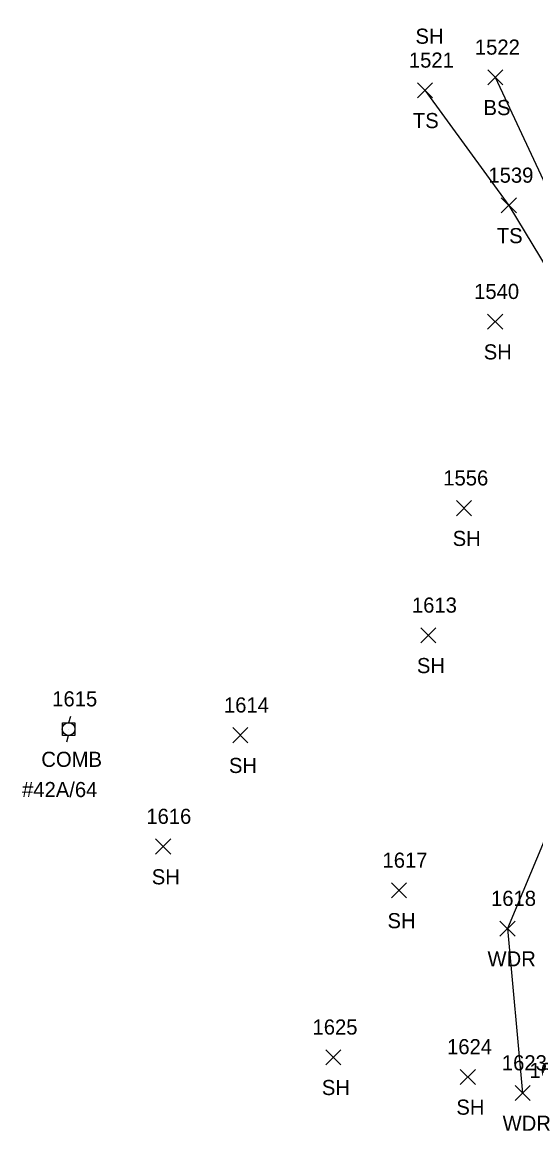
# Model space of a CAD drawing. Extents: x 1678553 to 1680768, y 787260 to 792325.
# Drawn here: x 1678553.1 to 1678621, y 787278.6 to 787425.2 of the extents above; entities that cross this region are included whole.
import ezdxf

# ---------------------------------------------------------------- set-up
doc = ezdxf.new("R2010")
doc.units = 0
for name, color, linetype in [('L_A', 7, 'Continuous'), ('L_I', 7, 'Continuous'), ('L_TIC', 7, 'Continuous'), ('LAWA', 7, 'Continuous'), ('LELB', 7, 'Continuous'), ('U_A', 7, 'Continuous'), ('U_C', 7, 'Continuous'), ('U_I', 7, 'Continuous'), ('UP', 7, 'Continuous')]:
    doc.layers.add(name, color=color, linetype=linetype)

msp = doc.modelspace()

# ---------------------------------------------------------------- linework, layer by layer
at = {"layer": 'L_TIC'}
for points in [[(1678614.65, 787416.95), (1678616.65, 787418.95)], [(1678616.65, 787416.95), (1678614.65, 787418.95)], [(1678605.34, 787415.23), (1678607.34, 787417.23)], [(1678607.34, 787415.23), (1678605.34, 787417.23)], [(1678616.44, 787400.01), (1678618.44, 787402.01)], [(1678618.44, 787400.01), (1678616.44, 787402.01)], [(1678614.63, 787384.63), (1678616.63, 787386.63)], [(1678616.63, 787384.63), (1678614.63, 787386.63)], [(1678610.52, 787359.96), (1678612.52, 787361.96)], [(1678612.52, 787359.96), (1678610.52, 787361.96)], [(1678605.79, 787343.14), (1678607.79, 787345.14)], [(1678607.79, 787343.14), (1678605.79, 787345.14)], [(1678580.92, 787329.93), (1678582.92, 787331.93)], [(1678582.92, 787329.93), (1678580.92, 787331.93)], [(1678570.71, 787315.2), (1678572.71, 787317.2)], [(1678572.71, 787315.2), (1678570.71, 787317.2)], [(1678601.9, 787309.4), (1678603.9, 787311.4)], [(1678603.9, 787309.4), (1678601.9, 787311.4)], [(1678616.26, 787304.35), (1678618.26, 787306.35)], [(1678618.26, 787304.35), (1678616.26, 787306.35)], [(1678593.21, 787287.33), (1678595.21, 787289.33)], [(1678595.21, 787287.33), (1678593.21, 787289.33)], [(1678611.01, 787284.73), (1678613.01, 787286.73)], [(1678613.01, 787284.73), (1678611.01, 787286.73)], [(1678618.26, 787282.6), (1678620.26, 787284.6)], [(1678620.26, 787282.6), (1678618.26, 787284.6)]]:
    msp.add_lwpolyline(points, dxfattribs=at)
at = {"layer": 'LAWA'}
msp.add_lwpolyline([(1678664.87, 787478.76), (1678656.17, 787475.05), (1678649.55, 787452.64), (1678645.06, 787437.85), (1678645.53, 787417.53), (1678643.94, 787403.04), (1678640.14, 787385.56), (1678638.68, 787382.05), (1678636.34, 787358.01), (1678630, 787335.83), (1678617.26, 787305.35), (1678619.26, 787283.6)], dxfattribs=at)
at = {"layer": 'LELB'}
for points in [[(1678615.65, 787417.95), (1678623.59, 787400.99), (1678633.57, 787392.81), (1678638.68, 787382.05)], [(1678606.34, 787416.23), (1678617.44, 787401.01), (1678626.85, 787385.47), (1678635.93, 787378.61), (1678632.1, 787358.6), (1678630, 787335.83)]]:
    msp.add_lwpolyline(points, dxfattribs=at)
at = {"layer": 'UP'}
for p, q in [((1678558.37, 787330.9), (1678558.37, 787332.57)), ((1678558.37, 787332.57), (1678560.03, 787332.57)), ((1678559.45, 787333.4), (1678559.2, 787332.57)), ((1678560.03, 787332.57), (1678560.03, 787330.9)), ((1678559.2, 787331.74), (1678559.2, 787331.74)), ((1678560.03, 787330.9), (1678558.37, 787330.9)), ((1678558.95, 787330.07), (1678559.2, 787330.9))]:
    msp.add_line(p, q, dxfattribs=at)
msp.add_circle((1678559.2, 787331.74), 0.833, dxfattribs=at)

# ---------------------------------------------------------------- texts
at = {"layer": 'L_A'}
for s, p in [('SH', (1678605.09, 787422.39)), ('BS', (1678614.09, 787412.95)), ('TS', (1678604.75, 787411.23)), ('TS', (1678615.85, 787396.01)), ('SH', (1678614.12, 787380.63)), ('SH', (1678610.01, 787355.96)), ('SH', (1678605.28, 787339.14)), ('SH', (1678580.41, 787325.93)), ('SH', (1678570.2, 787311.2)), ('SH', (1678601.39, 787305.4)), ('WDR', (1678614.62, 787300.35)), ('SH', (1678592.7, 787283.33)), ('SH', (1678610.5, 787280.73)), ('WDR', (1678616.62, 787278.6))]:
    msp.add_text(s, height=2, dxfattribs=at).set_placement(p)
at = {"layer": 'L_I'}
for s, p in [('1522', (1678612.95, 787420.95)), ('1521', (1678604.22, 787419.23)), ('1539', (1678614.74, 787404.01)), ('1540', (1678612.85, 787388.63)), ('1556', (1678608.77, 787363.96)), ('1613', (1678604.62, 787347.14)), ('1614', (1678579.75, 787333.93)), ('1616', (1678569.48, 787319.2)), ('1617', (1678600.73, 787313.4)), ('1618', (1678615.09, 787308.35)), ('1625', (1678591.47, 787291.33)), ('1624', (1678609.27, 787288.73)), ('1623', (1678616.52, 787286.6)), ('1622', (1678620.17, 787285.59))]:
    msp.add_text(s, height=2, dxfattribs=at).set_placement(p)
at = {"layer": 'U_A'}
msp.add_text('COMB', height=2, dxfattribs=at).set_placement((1678555.59, 787326.74))
at = {"layer": 'U_C'}
msp.add_text('#42A/64', height=2, dxfattribs=at).set_placement((1678553.04, 787322.74))
at = {"layer": 'U_I'}
msp.add_text('1615', height=2, dxfattribs=at).set_placement((1678557.03, 787334.74))

doc.saveas('drawing.dxf')
